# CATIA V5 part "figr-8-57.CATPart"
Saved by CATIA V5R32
Part number: Part1
Bounding box of the stored display mesh (mm): x -50.499 to 50.499, y -68.48 to 68.48, z -46 to 50
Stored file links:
  D:\PROJECTS\Project 2022\CATIA V5 6R 2022\Resources\Part Files\c08_catia_v5_6r2022_prt\figr-8-57.CATPart
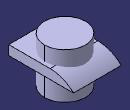
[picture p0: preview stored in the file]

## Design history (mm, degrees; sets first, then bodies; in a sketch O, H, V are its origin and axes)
Body1 (main body)
  Sketch1 on xy-plane, origin (0, 0, 0), H (1, 0, 0), V (0, 1, 0)
    line L1 (-50.499, 68.4797) -> (50.499, 68.4797)
    line L2 (50.499, 68.4797) -> (50.499, -68.4797)
    line L3 (50.499, -68.4797) -> (-50.499, -68.4797)
    line L4 (-50.499, -68.4797) -> (-50.499, 68.4797)
    axis line L5 (50.499, -68.4797) -> (-50.499, 68.4797)
    horizontal: L1 H, L3 H
    vertical: L2 V, L4 V
    midpoint: O L5
  Pad1: profile Sketch1, direction (0, 0, 1), length 20
  Fillet1: radius 71, on edge [face of Pad1 | face of Pad1]
Body2
  Sketch2 on xy-plane, origin (0, 0, 0), H (1, 0, 0), V (0, 1, 0)
    circle A1 centre (0, 0) radius 43.2524
    point P1 (0, 43.2524)
    coincidence: A1 P1, P1 V
  Pad2: profile Sketch2, direction (0, 0, 1), length 50, opposite side length 46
